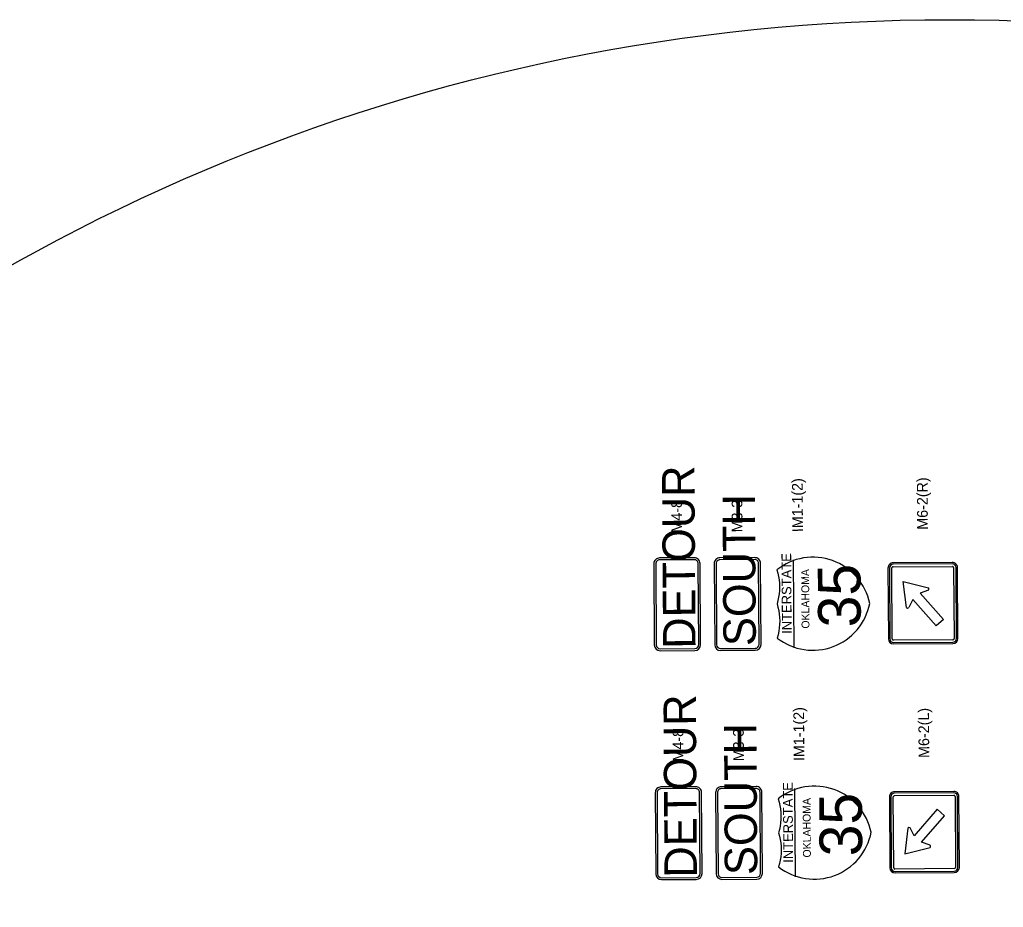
# Model space of a CAD drawing. Extents: x 2135767 to 2151731, y 141839 to 175894.
# Drawn here: x 2137979 to 2140190, y 173899 to 175894 of the extents above; entities that cross this region are included whole.
import ezdxf

# ---------------------------------------------------------------- set-up
doc = ezdxf.new("R2010")
doc.units = 0
doc.layers.add('PR_Phasing_Detour_1', color=7, linetype='Continuous')

msp = doc.modelspace()

# ---------------------------------------------------------------- linework, layer by layer
at = {"layer": 'PR_Phasing_Detour_1'}
for p, q in [((2139495.5, 174684.3), (2139417.3, 174683.8)), ((2139631.2, 174684.7), (2139553.1, 174684.2)), ((2139404.4, 174670.7), (2139405.5, 174488.3)), ((2139408.7, 174670.7), (2139409.8, 174488.4)), ((2139495.5, 174679.9), (2139417.3, 174679.4)), ((2139505.3, 174489), (2139504.2, 174671.3)), ((2139509.7, 174489), (2139508.6, 174671.3)), ((2139540.1, 174671.1), (2139541.3, 174488.8)), ((2139544.5, 174671.2), (2139545.6, 174488.8)), ((2139631.2, 174680.4), (2139553.1, 174679.9)), ((2139641.1, 174489.4), (2139640, 174671.7)), ((2139645.5, 174489.4), (2139644.3, 174671.8)), ((2139719.8, 174481.6), (2139718.5, 174679.9)), ((2139930.9, 174661.2), (2139931.9, 174502)), ((2139934.2, 174661.2), (2139935.1, 174502)), ((2139934.2, 174661.2), (2139935.1, 174502)), ((2139940.6, 174502), (2139939.6, 174661.3)), ((2139940.6, 174502), (2139939.6, 174661.3)), ((2140075.6, 174673.7), (2139942.4, 174672.8)), ((2140075.6, 174670.4), (2139942.4, 174669.6)), ((2140075.6, 174670.4), (2139942.4, 174669.6)), ((2139942.4, 174664.2), (2140075.6, 174665)), ((2139942.4, 174664.2), (2140075.6, 174665)), ((2140078.5, 174662.1), (2140079.5, 174502.9)), ((2140078.5, 174662.1), (2140079.5, 174502.9)), ((2140084.9, 174502.9), (2140083.9, 174662.2)), ((2140084.9, 174502.9), (2140083.9, 174662.2)), ((2140088.2, 174503), (2140087.2, 174662.2)), ((2139972.3, 174572.6), (2139965.3, 174630.7)), ((2139965.3, 174630.7), (2140022.1, 174616.8)), ((2140076.6, 174500), (2139943.4, 174499.2)), ((2140076.6, 174500), (2139943.4, 174499.2)), ((2139943.5, 174493.8), (2140076.7, 174494.6)), ((2139943.5, 174493.8), (2140076.7, 174494.6)), ((2139943.5, 174490.5), (2140076.7, 174491.3)), ((2139418.6, 174479.7), (2139496.7, 174480.2)), ((2139418.6, 174475.4), (2139496.7, 174475.9)), ((2139554.3, 174480.2), (2139632.5, 174480.7)), ((2139554.4, 174475.8), (2139632.5, 174476.3)), ((2139407.6, 174156.2), (2139408.7, 173973.8)), ((2139411.9, 174156.2), (2139413, 173973.8)), ((2139498.6, 174169.7), (2139420.5, 174169.3)), ((2139498.7, 174165.4), (2139420.5, 174164.9)), ((2139508.5, 173974.4), (2139507.4, 174156.8)), ((2139512.9, 173974.5), (2139511.7, 174156.8)), ((2139543.3, 174156.6), (2139544.5, 173974.3)), ((2139547.7, 174156.6), (2139548.8, 173974.3)), ((2139634.4, 174170.2), (2139556.3, 174169.7)), ((2139634.4, 174165.8), (2139556.3, 174165.4)), ((2139644.3, 173974.9), (2139643.2, 174157.2)), ((2139648.6, 173974.9), (2139647.5, 174157.2)), ((2139723, 173967), (2139721.7, 174165.4)), ((2140078.8, 174159.1), (2139945.6, 174158.3)), ((2140078.8, 174155.9), (2139945.6, 174155.1)), ((2140078.8, 174155.9), (2139945.6, 174155.1)), ((2139934.1, 174146.7), (2139935.1, 173987.5)), ((2139937.3, 174146.7), (2139938.3, 173987.5)), ((2139937.3, 174146.7), (2139938.3, 173987.5)), ((2139943.8, 173987.5), (2139942.8, 174146.8)), ((2139943.8, 173987.5), (2139942.8, 174146.8)), ((2139945.6, 174149.6), (2140078.8, 174150.5)), ((2139945.6, 174149.6), (2140078.8, 174150.5)), ((2140081.7, 174147.6), (2140082.7, 173988.4)), ((2140081.7, 174147.6), (2140082.7, 173988.4)), ((2140088.1, 173988.4), (2140087.1, 174147.7)), ((2140088.1, 173988.4), (2140087.1, 174147.7)), ((2140091.4, 173988.4), (2140090.4, 174147.7)), ((2139975.4, 174076.6), (2139969.1, 174018.5)), ((2139969.1, 174018.5), (2140025.7, 174033)), ((2140079.8, 173985.5), (2139946.6, 173984.7)), ((2140079.8, 173985.5), (2139946.6, 173984.7)), ((2139946.7, 173979.2), (2140079.9, 173980.1)), ((2139946.7, 173979.2), (2140079.9, 173980.1)), ((2139946.7, 173976), (2140079.9, 173976.8)), ((2139421.8, 173965.2), (2139499.9, 173965.7)), ((2139421.8, 173960.9), (2139499.9, 173961.4)), ((2139557.5, 173965.7), (2139635.7, 173966.1)), ((2139557.6, 173961.3), (2139635.7, 173961.8))]:
    msp.add_line(p, q, dxfattribs=at)
for points in [[(2139681.9, 174503.9), (2139688.6, 174499), (2139695.6, 174494.5), (2139702.9, 174490.5), (2139710.4, 174487), (2139718.2, 174484), (2139726.1, 174481.4), (2139734.1, 174479.4), (2139742.3, 174477.9), (2139750.5, 174476.9), (2139758.8, 174476.4), (2139767.1, 174476.5), (2139775.4, 174477.1), (2139783.6, 174478.2), (2139791.8, 174479.8), (2139799.8, 174482), (2139807.7, 174484.6), (2139815.3, 174487.8), (2139822.8, 174491.4), (2139830, 174495.6), (2139837, 174500.1), (2139843.6, 174505.1), (2139849.9, 174510.5), (2139855.8, 174516.3), (2139861.4, 174522.5), (2139866.6, 174529), (2139871.3, 174535.8), (2139875.6, 174542.9), (2139879.4, 174550.3), (2139882.8, 174557.9), (2139885.6, 174565.7), (2139888, 174573.6), (2139889.8, 174581.7), (2139887.9, 174589.8), (2139885.4, 174597.7), (2139882.5, 174605.5), (2139879, 174613.1), (2139875.1, 174620.4), (2139870.7, 174627.4), (2139865.9, 174634.2), (2139860.7, 174640.6), (2139855, 174646.7), (2139849, 174652.5), (2139842.6, 174657.8), (2139835.9, 174662.7), (2139829, 174667.2), (2139821.7, 174671.2), (2139814.2, 174674.7), (2139806.5, 174677.8), (2139798.6, 174680.4), (2139790.5, 174682.4), (2139782.4, 174684), (2139774.1, 174685), (2139765.8, 174685.5), (2139757.5, 174685.4), (2139749.2, 174684.9), (2139741, 174683.8), (2139732.9, 174682.1), (2139724.8, 174680), (2139717, 174677.4), (2139709.3, 174674.2), (2139701.8, 174670.6), (2139694.6, 174666.5), (2139687.6, 174662), (2139681, 174657), (2139683.1, 174649.5), (2139684.7, 174641.9), (2139685.9, 174634.3), (2139686.7, 174626.5), (2139687, 174618.8), (2139686.8, 174611), (2139686.1, 174603.2), (2139685, 174595.6), (2139683.5, 174587.9), (2139681.4, 174580.4), (2139683.6, 174573), (2139685.2, 174565.4), (2139686.4, 174557.7), (2139687.2, 174550), (2139687.4, 174542.2), (2139687.3, 174534.4), (2139686.6, 174526.7), (2139685.5, 174519), (2139683.9, 174511.4), (2139681.9, 174503.9)], [(2139965.3, 174630.7), (2140022.1, 174616.8)], [(2139972.3, 174572.6), (2139965.3, 174630.7)], [(2140021.8, 174611.6), (2140003.1, 174604.8), (2140055.6, 174545.7), (2140039, 174531), (2139986.5, 174590.1), (2139977.5, 174572.3)], [(2140021.8, 174611.6), (2140003.1, 174604.8), (2140055.6, 174545.7), (2140039, 174531), (2139986.5, 174590.1), (2139977.5, 174572.3)], [(2139685.1, 173989.4), (2139691.8, 173984.5), (2139698.8, 173980), (2139706.1, 173976), (2139713.6, 173972.5), (2139721.4, 173969.4), (2139729.3, 173966.9), (2139737.3, 173964.9), (2139745.5, 173963.3), (2139753.7, 173962.4), (2139762, 173961.9), (2139770.3, 173961.9), (2139778.6, 173962.5), (2139786.8, 173963.7), (2139795, 173965.3), (2139803, 173967.5), (2139810.9, 173970.1), (2139818.5, 173973.3), (2139826, 173976.9), (2139833.2, 173981), (2139840.2, 173985.6), (2139846.8, 173990.6), (2139853.1, 173996), (2139859, 174001.8), (2139864.6, 174007.9), (2139869.8, 174014.5), (2139874.5, 174021.3), (2139878.8, 174028.4), (2139882.6, 174035.8), (2139886, 174043.4), (2139888.8, 174051.2), (2139891.2, 174059.1), (2139893, 174067.2), (2139891.1, 174075.3), (2139888.6, 174083.2), (2139885.7, 174091), (2139882.2, 174098.5), (2139878.3, 174105.9), (2139873.9, 174112.9), (2139869.1, 174119.7), (2139863.9, 174126.1), (2139858.2, 174132.2), (2139852.2, 174137.9), (2139845.8, 174143.3), (2139839.1, 174148.2), (2139832.1, 174152.6), (2139824.9, 174156.7), (2139817.4, 174160.2), (2139809.7, 174163.3), (2139801.8, 174165.8), (2139793.7, 174167.9), (2139785.5, 174169.4), (2139777.3, 174170.5), (2139769, 174170.9), (2139760.7, 174170.9), (2139752.4, 174170.3), (2139744.2, 174169.2), (2139736.1, 174167.6), (2139728, 174165.5), (2139720.2, 174162.8), (2139712.5, 174159.7), (2139705, 174156.1), (2139697.8, 174152), (2139690.8, 174147.4), (2139684.2, 174142.5), (2139686.3, 174135), (2139687.9, 174127.4), (2139689.1, 174119.7), (2139689.9, 174112), (2139690.2, 174104.2), (2139690, 174096.5), (2139689.3, 174088.7), (2139688.2, 174081), (2139686.7, 174073.4), (2139684.6, 174065.9), (2139686.7, 174058.4), (2139688.4, 174050.8), (2139689.6, 174043.2), (2139690.4, 174035.4), (2139690.6, 174027.7), (2139690.4, 174019.9), (2139689.8, 174012.2), (2139688.7, 174004.5), (2139687.1, 173996.9), (2139685.1, 173989.4)], [(2140025.4, 174038.2), (2140006.5, 174044.7), (2140058.3, 174104.5), (2140041.5, 174119), (2139989.8, 174059.3), (2139980.6, 174077)], [(2140025.4, 174038.2), (2140006.5, 174044.7), (2140058.3, 174104.5), (2140041.5, 174119), (2139989.8, 174059.3), (2139980.6, 174077)], [(2139975.4, 174076.6), (2139969.1, 174018.5)], [(2139969.1, 174018.5), (2140025.7, 174033)]]:
    msp.add_lwpolyline(points, dxfattribs=at)
msp.add_circle((2140069.5, 171591.4), 4302.2, dxfattribs=at)
for centre, radius, start, end in [((2139417.4, 174670.8), 13, 90.3555, 180.3555), ((2139495.5, 174671.2), 13, 0.3555, 90.3555), ((2139553.2, 174671.2), 13, 90.3555, 180.3555), ((2139631.3, 174671.7), 13, 0.3555, 90.3555), ((2139417.4, 174670.8), 8.68, 90.3555, 180.3555), ((2139495.5, 174671.2), 8.68, 0.3555, 90.3555), ((2139553.2, 174671.2), 8.68, 90.3555, 180.3555), ((2139631.3, 174671.7), 8.68, 0.3555, 90.3555), ((2139942.4, 174661.3), 11.5, 90.3555, 180.3555), ((2139942.4, 174661.3), 8.29, 90.3555, 180.3555), ((2139942.4, 174661.3), 8.29, 90.3555, 180.3555), ((2139942.4, 174661.3), 2.86, 90.3555, 180.3555), ((2139942.4, 174661.3), 2.86, 90.3555, 180.3555), ((2140075.6, 174662.1), 11.5, 0.3555, 90.3555), ((2140075.6, 174662.1), 8.29, 0.3555, 90.3555), ((2140075.6, 174662.1), 8.29, 0.3555, 90.3555), ((2140075.6, 174662.1), 2.86, 0.3555, 90.3555), ((2140075.6, 174662.1), 2.86, 0.3555, 90.3555), ((2140019.3, 174614.4), 3.7, 311.6142, 41.6142), ((2140019.3, 174614.4), 3.7, 311.6142, 41.6142), ((2139975.1, 174575), 3.7, 221.6142, 311.6142), ((2139975.1, 174575), 3.7, 221.6142, 311.6142), ((2139418.5, 174488.4), 13, 180.3555, 270.3555), ((2139418.5, 174488.4), 8.68, 180.3555, 270.3555), ((2139496.7, 174488.9), 13, 270.3555, 0.3555), ((2139496.7, 174488.9), 8.68, 270.3555, 0.3555), ((2139554.3, 174488.9), 13, 180.3555, 270.3555), ((2139554.3, 174488.9), 8.68, 180.3555, 270.3555), ((2139632.4, 174489.4), 8.68, 270.3555, 0.3555), ((2139632.4, 174489.4), 13, 270.3555, 0.3555), ((2139943.4, 174502.1), 11.5, 180.3555, 270.3555), ((2139943.4, 174502.1), 8.29, 180.3555, 270.3555), ((2139943.4, 174502.1), 8.29, 180.3555, 270.3555), ((2139943.4, 174502.1), 2.86, 180.3555, 270.3555), ((2139943.4, 174502.1), 2.86, 180.3555, 270.3555), ((2140076.6, 174502.9), 2.86, 270.3555, 0.3555), ((2140076.6, 174502.9), 2.86, 270.3555, 0.3555), ((2140076.6, 174502.9), 11.5, 270.3555, 0.3555), ((2140076.6, 174502.9), 8.29, 270.3555, 0.3555), ((2140076.6, 174502.9), 8.29, 270.3555, 0.3555), ((2139420.6, 174156.2), 13, 90.3555, 180.3555), ((2139420.6, 174156.2), 8.68, 90.3555, 180.3555), ((2139498.7, 174156.7), 13, 0.3555, 90.3555), ((2139498.7, 174156.7), 8.68, 0.3555, 90.3555), ((2139556.3, 174156.7), 13, 90.3555, 180.3555), ((2139556.3, 174156.7), 8.68, 90.3555, 180.3555), ((2139634.5, 174157.2), 13, 0.3555, 90.3555), ((2139634.5, 174157.2), 8.68, 0.3555, 90.3555), ((2139945.6, 174146.8), 11.5, 90.3555, 180.3555), ((2139945.6, 174146.8), 8.29, 90.3555, 180.3555), ((2139945.6, 174146.8), 8.29, 90.3555, 180.3555), ((2140078.8, 174147.6), 11.5, 0.3555, 90.3555), ((2140078.8, 174147.6), 8.29, 0.3555, 90.3555), ((2140078.8, 174147.6), 8.29, 0.3555, 90.3555), ((2139945.6, 174146.8), 2.86, 90.3555, 180.3555), ((2139945.6, 174146.8), 2.86, 90.3555, 180.3555), ((2140078.8, 174147.6), 2.86, 0.3555, 90.3555), ((2140078.8, 174147.6), 2.86, 0.3555, 90.3555), ((2139978.2, 174074.2), 3.7, 49.0968, 139.0968), ((2139978.2, 174074.2), 3.7, 49.0968, 139.0968), ((2140022.9, 174035.4), 3.7, 319.0968, 49.0968), ((2140022.9, 174035.4), 3.7, 319.0968, 49.0968), ((2139421.7, 173973.9), 13, 180.3555, 270.3555), ((2139421.7, 173973.9), 8.68, 180.3555, 270.3555), ((2139499.9, 173974.4), 13, 270.3555, 0.3555), ((2139499.9, 173974.4), 8.68, 270.3555, 0.3555), ((2139557.5, 173974.3), 13, 180.3555, 270.3555), ((2139557.5, 173974.3), 8.68, 180.3555, 270.3555), ((2139635.6, 173974.8), 8.68, 270.3555, 0.3555), ((2139635.6, 173974.8), 13, 270.3555, 0.3555), ((2139946.6, 173987.5), 11.5, 180.3555, 270.3555), ((2139946.6, 173987.5), 8.29, 180.3555, 270.3555), ((2139946.6, 173987.5), 8.29, 180.3555, 270.3555), ((2139946.6, 173987.5), 2.86, 180.3555, 270.3555), ((2139946.6, 173987.5), 2.86, 180.3555, 270.3555), ((2140079.8, 173988.4), 2.86, 270.3555, 0.3555), ((2140079.8, 173988.4), 2.86, 270.3555, 0.3555), ((2140079.8, 173988.4), 11.5, 270.3555, 0.3555), ((2140079.8, 173988.4), 8.29, 270.3555, 0.3555), ((2140079.8, 173988.4), 8.29, 270.3555, 0.3555)]:
    msp.add_arc(centre, radius, start, end, dxfattribs=at)

# ---------------------------------------------------------------- texts
for s, height, p in [('DETOUR', 72.94, (2139498.2, 174480)), ('IM1-1(2)', 24, (2139739.7, 174741.9)), ('M6-2(R)', 24, (2140020.5, 174747.4)), ('SOUTH', 72.94, (2139633.9, 174486)), ('M4-8', 24, (2139468, 174741)), ('M3-3', 24, (2139603.8, 174741.5)), ('INTERSTATE', 21.78, (2139714.3, 174513.3)), ('35', 95.86, (2139869.7, 174528.1)), ('OKLAHOMA', 17.65, (2139754.3, 174525.1)), ('DETOUR', 72.94, (2139501.4, 173965.5)), ('IM1-1(2)', 24, (2139742.9, 174227.4)), ('M6-2(L)', 24, (2140023.7, 174234.5)), ('M4-8', 24, (2139471.2, 174226.5)), ('SOUTH', 72.94, (2139637.1, 173971.4)), ('M3-3', 24, (2139607, 174226.9)), ('INTERSTATE', 21.78, (2139717.5, 173998.8)), ('35', 95.86, (2139872.9, 174013.5)), ('OKLAHOMA', 17.65, (2139757.5, 174010.6))]:
    msp.add_text(s, height=height, rotation=90.3555, dxfattribs=at).set_placement(p)

doc.saveas('drawing.dxf')
